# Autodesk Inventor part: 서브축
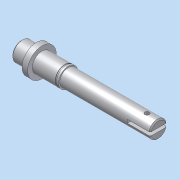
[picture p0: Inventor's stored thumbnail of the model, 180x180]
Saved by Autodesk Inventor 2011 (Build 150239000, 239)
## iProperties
Company: 한국ATC센터
Created: 2014-12
Part Number: 서브축
Document SubType Name: Modeling
Designer: KYOUNG IL JANG
Density: 1 g/cm^3
Mass: 23.2871 g
Surface Area: 76.512 cm^2
Volume: 23.2871 cm^3
Author: KYOUNG IL JANG
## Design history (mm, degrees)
sketch "스케치1"
  geometry: L1 (0, 0)-(120, 0); L2 (0, 0)-(0, 7.5); L3 (1, 8.5)-(13, 8.5); L4 (13, 8.5)-(13, 12.5); L5 (13, 12.5)-(18, 12.5); L6 (18, 12.5)-(18, 8.5); L7 (18, 8.5)-(41, 8.5); L8 (120, 7.5)-(120, 0); L9 (0, 7.5)-(1, 8.5); L10 (41, 8.5)-(41, 7.5); L11 (41, 7.5)-(120, 7.5); 1 further point
  constraints: 22 end point, 3 parallel, 3 perpendicular, 2 collinear, 2 point on line, 2 vertical, 1 horizontal
  dimensions: "d0" = 5 distance of L4.end L5.end; "d1" = 17 diameter of L7 L1; "d2" = 13 distance of point (0, 8.5) L3.end; "d3" = 25 diameter of L5 L1; "d4" = 120 distance of L1.start L1.end; "d5" = 1 distance of L2.end point (0, 8.5); "d6" = 1 distance of L3.start point (0, 8.5) (= d5); "d15" = 15 diameter of L11 L1; "d16" = 23 distance of L6.end L7.end
revolve "회전1" sketch "스케치1" stored, may be unused: angle "d9" = 90 deg
node "작업 평면1"
sketch "스케치2"
  geometry: L1 (11.5, 12.5)-(11.5, -12.5) reference; L2 (-3, 2.5)-(6, 2.5); L3 (6, -2.5)-(-3, -2.5); A1 r 2.5 centre (6, 0) between (6, -2.5) and (6, 2.5); A2 r 2.5 centre (-3, 0) between (-3, 2.5) and (-3, -2.5); 1 further point
  constraints: 4 end point, 4 point on circle, 4 tangent, 2 centre point, 1 horizontal alignment, 1 parallel, 1 perpendicular
  dimensions: "d10" = 5 distance between parallel lines of L3 L2; "d11" = 14 dimension on A1 A2; "d12" = 3 distance edge to line of A1 L1
extrude "돌출1" cut sketch "스케치2" distance "d13" = 3; taper "d14" = 0 deg
sketch "스케치3"
  geometry: L1 (18, -12.5)-(18, 12.5) reference; L2 (13, -12.5)-(13, 12.5) reference; L3 (18, 8.5)-(41, 8.5) reference; L4 (38, 8.5)-(39.15, 8.5); L5 (39.15, 8.5)-(39.15, 8.1); L6 (39.15, 8.1)-(38, 8.1); L7 (38, 8.1)-(38, 8.5); L8 (-24, 0)-(144, 0) reference; 1 further point
  constraints: 8 end point, 2 parallel, 1 horizontal, 1 perpendicular, 1 point on line
  dimensions: "d17" = 20 distance between parallel lines of L7 L1; "d18" = 1.15 distance of L5.end L6.end; "d19" = 8.1 distance between parallel lines of L6 L8
revolve "회전2" sketch "스케치3" stored, may be unused: angle "d20" = 90 deg
chamfer "모따기1" distance "d21" = 1; stored, may be unused: second distance "d22" = 2, angle "d23" = 45 deg
sketch "스케치4"
  geometry: L1 (-120, 1.5)-(-100, 1.5); L2 (-100, 1.5)-(-100, -1.5); L3 (-100, -1.5)-(-120, -1.5); L4 (-120, -1.5)-(-120, 1.5); L5 (-120, -6.5)-(-120, 6.5) reference; 2 further points
  constraints: 8 end point, 2 parallel, 1 collinear, 1 horizontal, 1 horizontal alignment, 1 midpoint, 1 perpendicular
  dimensions: "d24" = 3 distance between parallel lines of L3 L1; "d25" = 20 distance of L2.end L3.end
extrude "돌출2" cut sketch "스케치4" stored distance "d26" = 10; taper "d27" = 0 deg
sketch "스케치5"
  geometry: L1 (120, 6.325)-(120, -6.325) reference; C1 r 2 at (110, 0); 1 further point
  constraints: 1 centre point, 1 horizontal alignment
  dimensions: "d28" = 4 diameter of C1; "d29" = 10 distance from line of L1 C1.centre
extrude "돌출3" cut sketch "스케치5" stored distance "d30" = 10; taper "d31" = 0 deg
node "솔리드1"
node "투영된 루프1"
